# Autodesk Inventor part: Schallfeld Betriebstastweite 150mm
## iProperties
Shininess: 20.0
Length Units: 11269
Angle Units: 11279
Time Units: 11290
Mass Units: 11283
Length Display Precision: 2
Angle Display Precision: 2
Part Number: Schallfeld Betriebstastweite 150mm
Material: Lexan (klar)
Document SubType Name: Modellieren
Description: Schallfeld 0,15m
Checked By: Alves
Created: 2004-12
Designer: Ohle
Manufacturer: Standard
Standards Organization: Custom
Density: 0.0
Volumn: 0.0
Area: 0.0
PropertySet Name: Model Information
Control State: 0
Master: False
Checked Out: False
Last Check In By: ohle
Last Check In Date: 2005-08-23
ME: ST
Title: Schallfelder
Author: Ohle
Comments: keine Bemerkung
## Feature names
1. Blindzone_Aussenglocke [Revolution]
